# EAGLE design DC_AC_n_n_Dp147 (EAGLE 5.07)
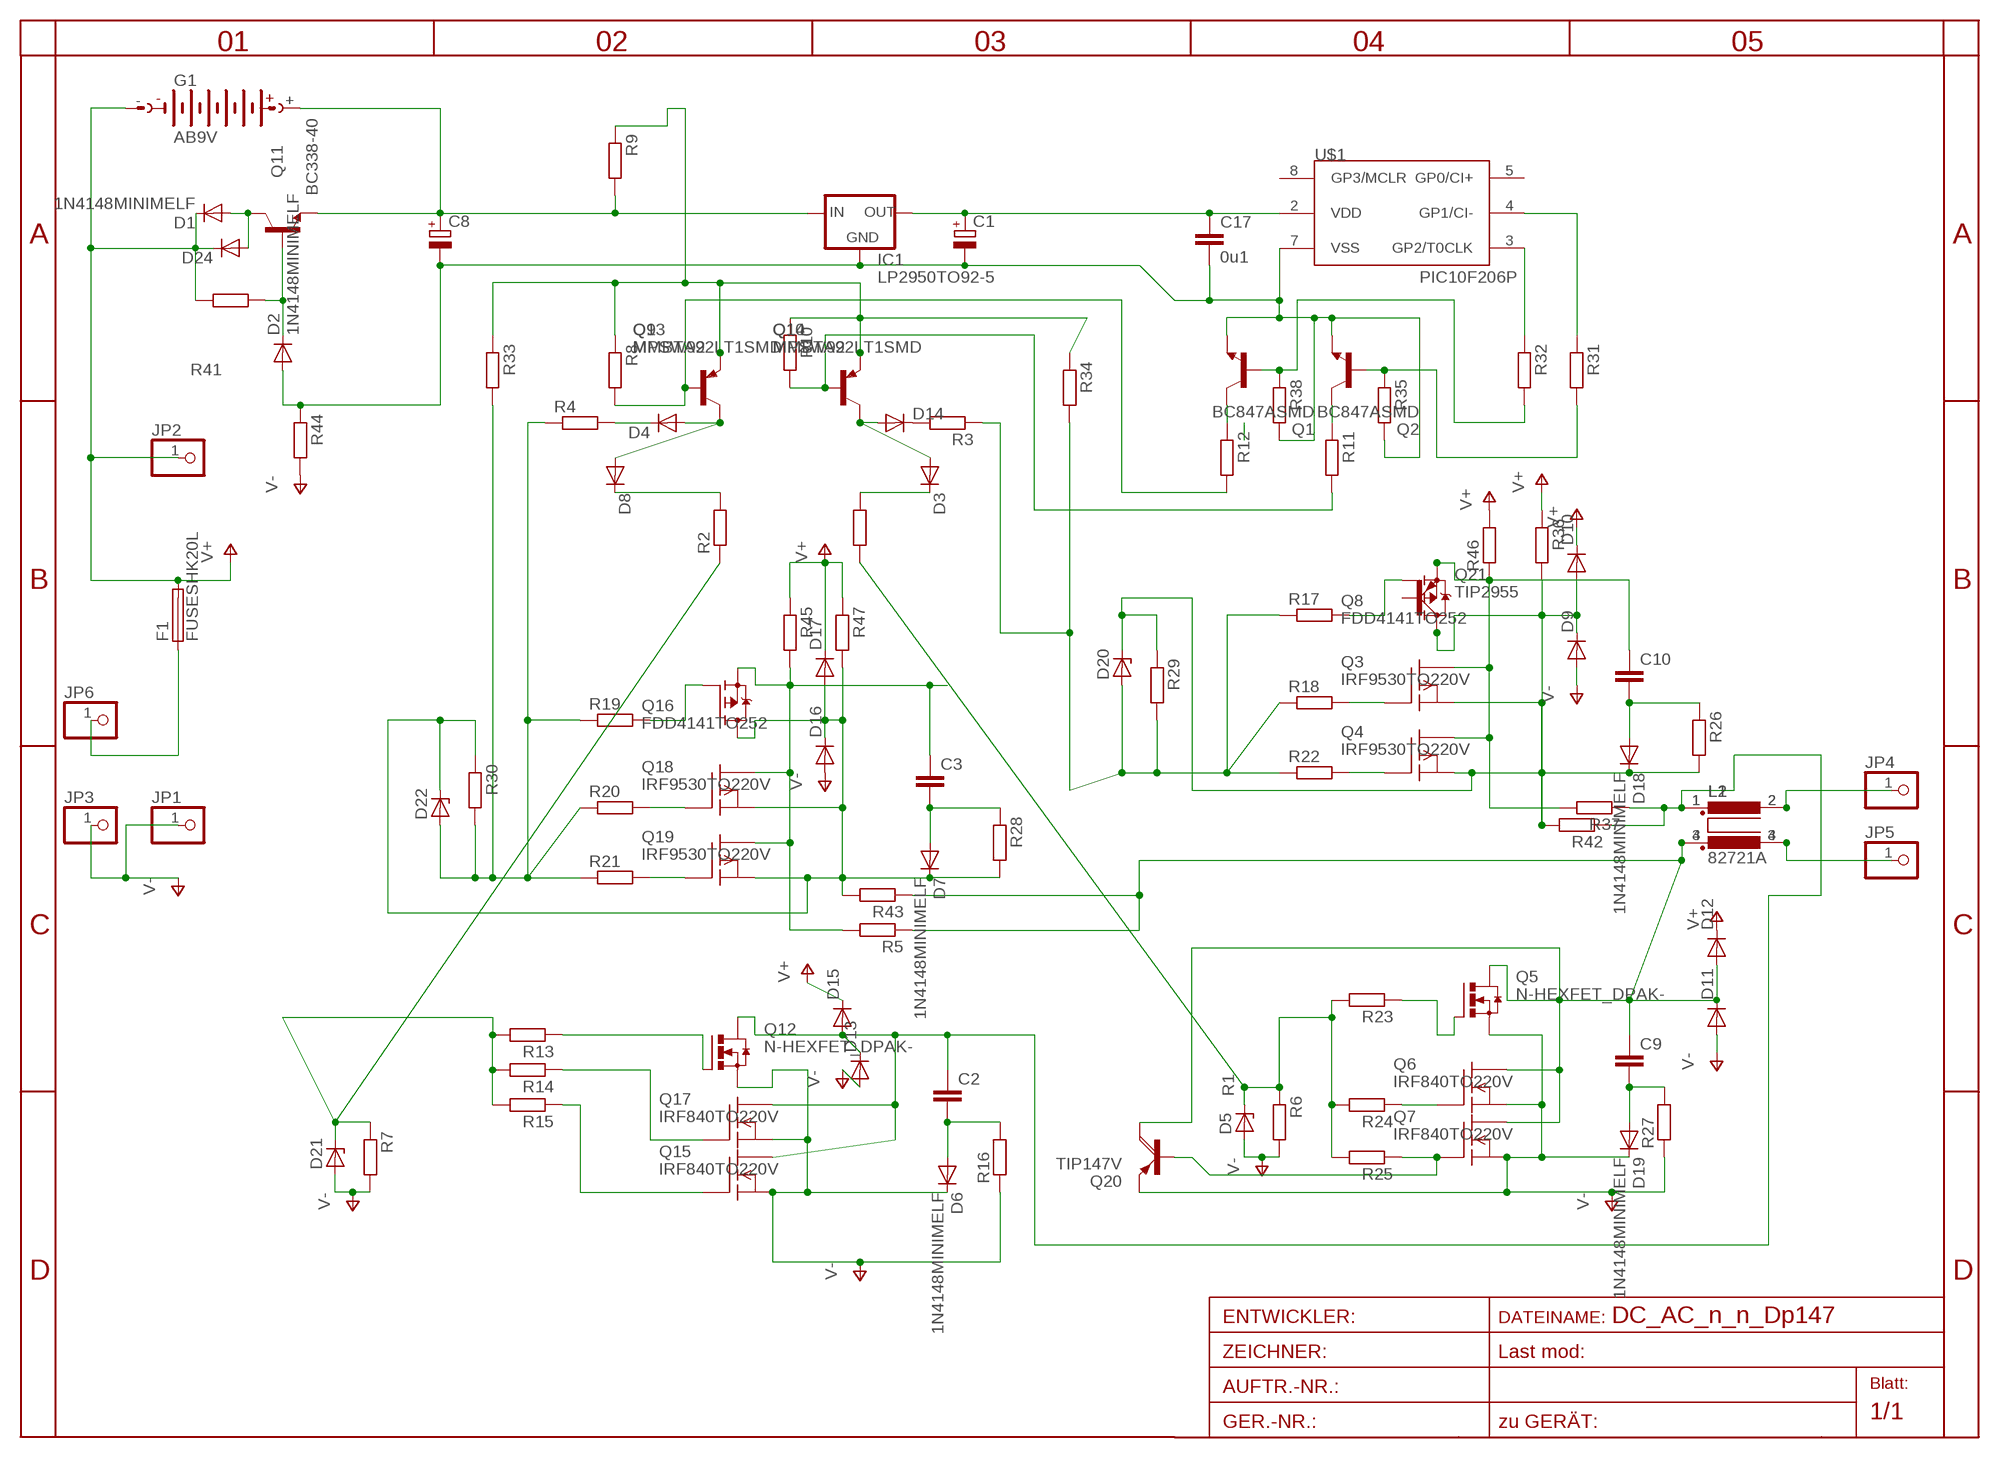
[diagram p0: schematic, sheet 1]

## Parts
C1  CPOL-EU5-13  [2,5-5-FLAT]
C2  C-EUC1812  [C1812]
C3  C-EUC1812K  [C1812K]
C8  CPOL-EUE2.5-7  [E2,5-7]
C9  C-EUC1812  [C1812]
C10  C-EUC1812K  [C1812K]
C17  0u1  C-EUC1206  [C1206]
D1  1N4148MINIMELF  [MINIMELF]
D2  1N4148MINIMELF  [MINIMELF]
D3  DIODE-SMB  [SMB]
D4  DIODE-SMB  [SMB]
D5  ZENER-DIODESOD80C  [SOD80C]
D6  1N4148MINIMELF  [MINIMELF]
D7  1N4148MINIMELF  [MINIMELF]
D8  DIODE-SMB  [SMB]
D9  DIODE-SMC  [SMC]
D10  DIODE-SMC  [SMC]
D11  DIODE-SMC  [SMC]
D12  DIODE-SMC  [SMC]
D13  DIODE-SMC  [SMC]
D14  DIODE-SMB  [SMB]
D15  DIODE-SMC  [SMC]
D16  DIODE-SMC  [SMC]
D17  DIODE-SMC  [SMC]
D18  1N4148MINIMELF  [MINIMELF]
D19  1N4148MINIMELF  [MINIMELF]
D20  ZENER-DIODESOD80C  [SOD80C]
D21  ZENER-DIODESOD80C  [SOD80C]
D22  ZENER-DIODESOD80C  [SOD80C]
D24  DIODE-D-7.5  [D-7.5]
F1  FUSESHK20L  [SHK20L]
G1  AB9V  [AB9V]
IC1  LP2950TO92-5  [T092-5]
JP1  PINHD-1X11MM6  [1X1MM8]
JP2  PINHD-1X11MM6  [1X1MM8]
JP3  PINHD-1X11MM6  [1X1MM8]
JP4  PINHD-1X14.5MM  [1X4MM5]
JP5  PINHD-1X14.5MM  [1X4MM5]
JP6  PINHD-1X11MM6  [1X1MM8]
L1  R1405VB2  [B2]
L2  82721A  [82721A]
Q1  BC847ASMD  [SOT23]
Q2  BC847ASMD  [SOT23]
Q3  IRF9530TO220V  [TO220V]
Q4  IRF9530TO220V  [TO220V]
Q5  N-HEXFET_DPAK-  [TO252]
Q6  IRF840TO220V  [TO220V]
Q7  IRF840TO220V  [TO220V]
Q8  FDD4141TO252  [TO252]
Q9  MPSW92  [TO92-CBE]
Q10  MPSW92  [TO92-CBE]
Q11  BC338-40  [TO92-EBC]
Q12  N-HEXFET_DPAK-  [TO252]
Q13  MMBTA92LT1SMD  [SOT23-BEC]
Q14  MMBTA92LT1SMD  [SOT23-BEC]
Q15  IRF840TO220V  [TO220V]
Q16  FDD4141TO252  [TO252]
Q17  IRF840TO220V  [TO220V]
Q18  IRF9530TO220V  [TO220V]
Q19  IRF9530TO220V  [TO220V]
Q20  TIP147V  [SOT93V]
Q21  TIP2955  [TOP3AV]
R1  R-EU_R1206  [R1206]
R2  R-EU_R1206  [R1206]
R3  R-EU_R1206  [R1206]
R4  R-EU_R1206  [R1206]
R5  R-EU_0207/30  [0207/30]
R6  R-EU_R1206  [R1206]
R7  R-EU_R1206  [R1206]
R8  R-EU_R1206  [R1206]
R9  R-EU_0207/10  [0207/10]
R10  R-EU_R1206  [R1206]
R11  R-EU_R1206  [R1206]
R12  R-EU_R1206  [R1206]
R13  R-EU_R1206  [R1206]
R14  R-EU_R1206  [R1206]
R15  R-EU_R1206  [R1206]
R16  R-EU_R1206  [R1206]
R17  R-EU_R1206  [R1206]
R18  R-EU_R1206  [R1206]
R19  R-EU_R1206  [R1206]
R20  R-EU_R1206  [R1206]
R21  R-EU_R1206  [R1206]
R22  R-EU_R1206  [R1206]
R23  R-EU_R1206  [R1206]
R24  R-EU_R1206  [R1206]
R25  R-EU_R1206  [R1206]
R26  R-EU_R1206  [R1206]
R27  R-EU_R1206  [R1206]
R28  R-EU_R1206  [R1206]
R29  R-EU_R1206  [R1206]
R30  R-EU_R1206  [R1206]
R31  R-EU_R1206  [R1206]
R32  R-EU_R1206  [R1206]
R33  R-EU_0207/30  [0207/30]
R34  R-EU_R1206  [R1206]
R35  R-EU_R0805  [R0805]
R36  R-EU_0207/10  [0207/10]
R37  R-EU_0207/10  [0207/10]
R38  R-EU_R0805  [R0805]
R41  R-EU_R1206  [R1206]
R42  R-EU_0207/15  [0207/15]
R43  R-EU_0207/30  [0207/30]
R44  R-EU_R1206  [R1206]
R45  R-EU_0204/5  [0204/5]
R46  R-EU_0204/5  [0204/5]
R47  R-EU_0204/5  [0204/5]
U$1  PIC10F206P  [DIL8]

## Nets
AC1: JP4.1 L1.2 L2.2
AC2: JP5.1 L1.4 L2.3
BATT+: C8.+ G1.+ IC1.3(IN) Q11.E R9.2
FNGATE2: D4.C R4.2
N$1: F1.1A JP6.1
N$2: C3.1 Q16.3(S) Q18.2(D) Q19.2(D) R5.2 R45.2
N$3: Q1.3(C) R12.1
N$4: Q3.1(G) R18.2
N$5: C1.+ C17.1 IC1.1(OUT) U$1.2(VDD)
N$6: D8.C R2.2
N$7: Q2.3(C) R11.1
N$8: D3.C R1.2
N$10: D5.C R1.1 R6.1 R23.2 R24.2 R25.2
N$11: Q8.1(G) R17.2
N$13: Q15.1(G) R15.1
N$15: Q17.1(G) R14.1
N$16: Q9.B Q13.B R8.2 R12.2
N$18: D4.A D8.A Q9.C Q13.C
N$19: Q10.B Q14.B R10.2 R11.2
N$21: D3.A D14.A Q10.C Q14.C
N$22: Q12.1(G) R13.1
N$23: Q4.1(G) R22.2
N$24: C10.2 D18.A R26.1
N$25: Q7.1(G) Q20.B R25.1
N$26: Q6.1(G) R24.1
N$27: Q5.1(G) R23.1
N$28: C9.2 D19.A R27.2
N$29: C2.2 D6.A R16.2
N$30: D7.C D16.C D17.A D22.C Q16.2(D) Q18.3(S) Q19.3(S) R28.2 R30.1 R43.2 R47.2
N$32: Q18.1(G) R20.2
N$33: Q19.1(G) R21.2
N$34: Q16.1(G) R19.2
N$35: C3.2 D7.A R28.1
N$36: D1.A D24.A Q11.C
N$38: D2.C Q11.B R41.1
N$39: R31.1 U$1.4(GP1/CI-)
N$42: Q2.1(B) R31.2 R35.1
N$43: R32.1 U$1.3(GP2/T0CLK)
N$45: Q1.1(B) R32.2 R38.1
N-GATE: D14.C R3.2
NDRAIN2: C2.1 D13.C D15.A L1.1 L2.1 Q12.3(D) Q15.2(D) Q17.2(D) R37.1 R42.1
NGATE2: D21.C R2.1 R7.1 R13.2 R14.2 R15.2
O1: C9.1 D11.C D12.A L1.3 L2.4 Q5.3(D) Q6.2(D) Q7.2(D) Q20.C R5.1 R43.1
P1E: D9.C D10.A D18.C D20.C Q3.3(S) Q4.3(S) Q8.2(D) Q21.C R26.2 R29.1 R36.2 R42.2
P-: C1.- C8.- C17.2 D2.A IC1.2(GND) Q1.2(E) Q2.2(E) R35.2 R38.2 R44.1 U$1.7(VSS)
PDRAIN1: C10.1 Q3.2(D) Q4.2(D) Q8.3(S) Q21.E R37.2 R46.1
PGATE1: D20.A R3.1 R17.1 R18.1 R22.1 R29.2 R34.2
PGATE2: D22.A R4.1 R19.1 R20.1 R21.1 R30.2 R33.2
V+: D1.C D10.C D12.C D15.C D17.C D24.C F1.2A G1.- JP2.1 R36.1 R41.2 R45.1 R46.2 R47.1
V-: D5.A D6.C D9.A D11.A D13.A D16.A D19.C D21.A JP1.1 JP3.1 Q5.2(S) Q6.3(S) Q7.3(S) Q12.2(S) Q15.3(S) Q17.3(S) Q20.E R6.2 R7.2 R16.1 R27.1 R44.2
VHIGH: Q9.E Q10.E Q13.E Q14.E R8.1 R9.1 R10.1 R33.1 R34.1
Unconnected: Q21.B U$1.5(GP0/CI+) U$1.8(GP3/MCLR)

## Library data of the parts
C1 C8 = rcl-2:CPOL-EU: POLARIZED CAPACITOR, European symbol
C2 C3 C9 C10 C17 = rcl-2:C-EU: CAPACITOR, European symbol
D1 D2 D6 D7 D18 D19 = diode-1:1N4148: DIODE
D3 D4 D8-D17 = diode:DIODE-: DIODE
D5 D20-D22 = diode:ZENER-DIODE: Z-Diode
D24 = diode-1:DIODE-: DIODE
F1 = fuse:FUSE: Fuse
G1 = battery:AB9V: 9-V BATTERY CLIP
IC1 = v-reg:LP2950?*: Source: http://cache.national.com/ds/LP/LP2950.pdf
JP1-JP6 = pinhead:PINHD-1X1: PIN HEADER
L1 = inductor-nkl:R1405V: Übertrager (verlustarm) bis typ. 400kHz Power transformer (low loss) up to typ. 400kHz
L2 = inductors:82721A: FILTER
Q1 Q2 = transistor-npn:BC847*: NPN Transistor
Q3 Q4 Q18 Q19 = transistor-fet:IRF9530: P-Channel Enhancement MOSFET (HEXFET); -100V; -12A; 0,3Ohm
Q5 Q12 = transistor-power:N-HEXFET_?-*: HEXFET® Power MOSFET
Q6 Q7 Q15 Q17 = transistor-fet:IRF840: N-Channel Enhancement MOSFET (HEXFET); 500V; 8A; 0,85Ohm
Q8 Q16 = transistor-fet:FDD4141: P-Channel PowerTrench® MOSFET Source: FDD4141.pdf
Q9 Q10 = transistor-pnp:MPSW92*: PNP Transistror
Q11 = transistor-npn:BC338*: NPN Transistor
Q13 Q14 = transistor-pnp:MMBTA92*: PNP Transistror
Q20 = transistor-power:TIP147: PNP DARLINGTON TRANSISTOR
Q21 = transistor-power:TIP2955: PNP TRANSISTOR
R1-R38 R41-R47 = rcl-2:R-EU_: RESISTOR, European symbol
U$1 = microchip-5:PIC10F2*: uPC nW 0,25/0,5k Program Flash memory Comparator

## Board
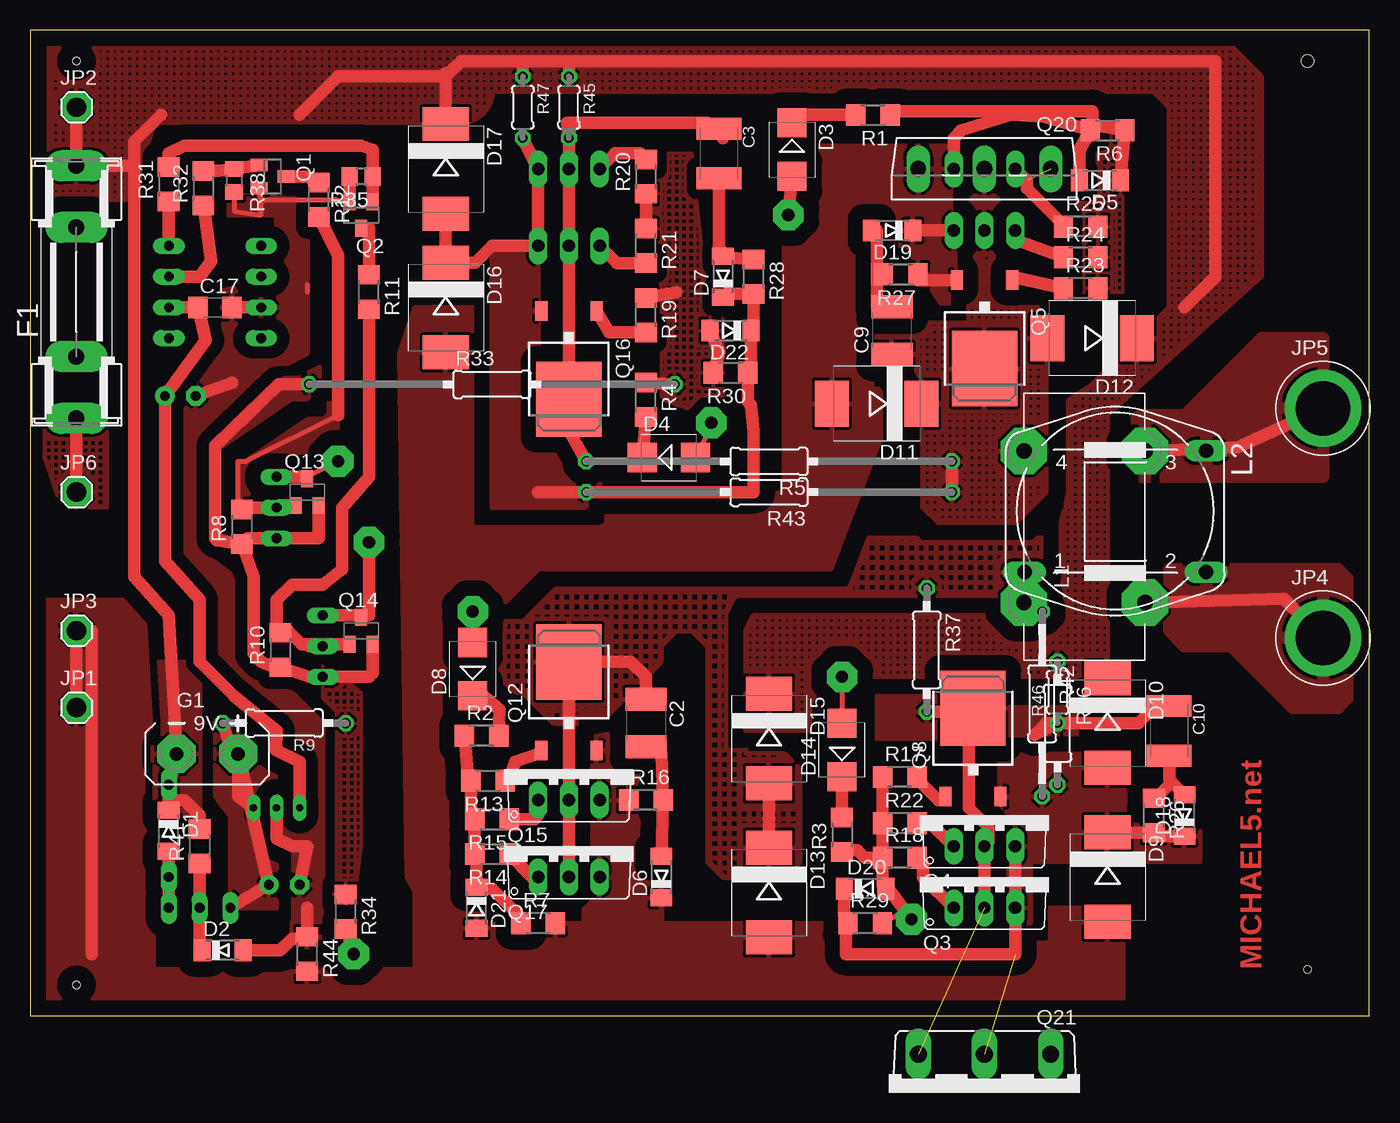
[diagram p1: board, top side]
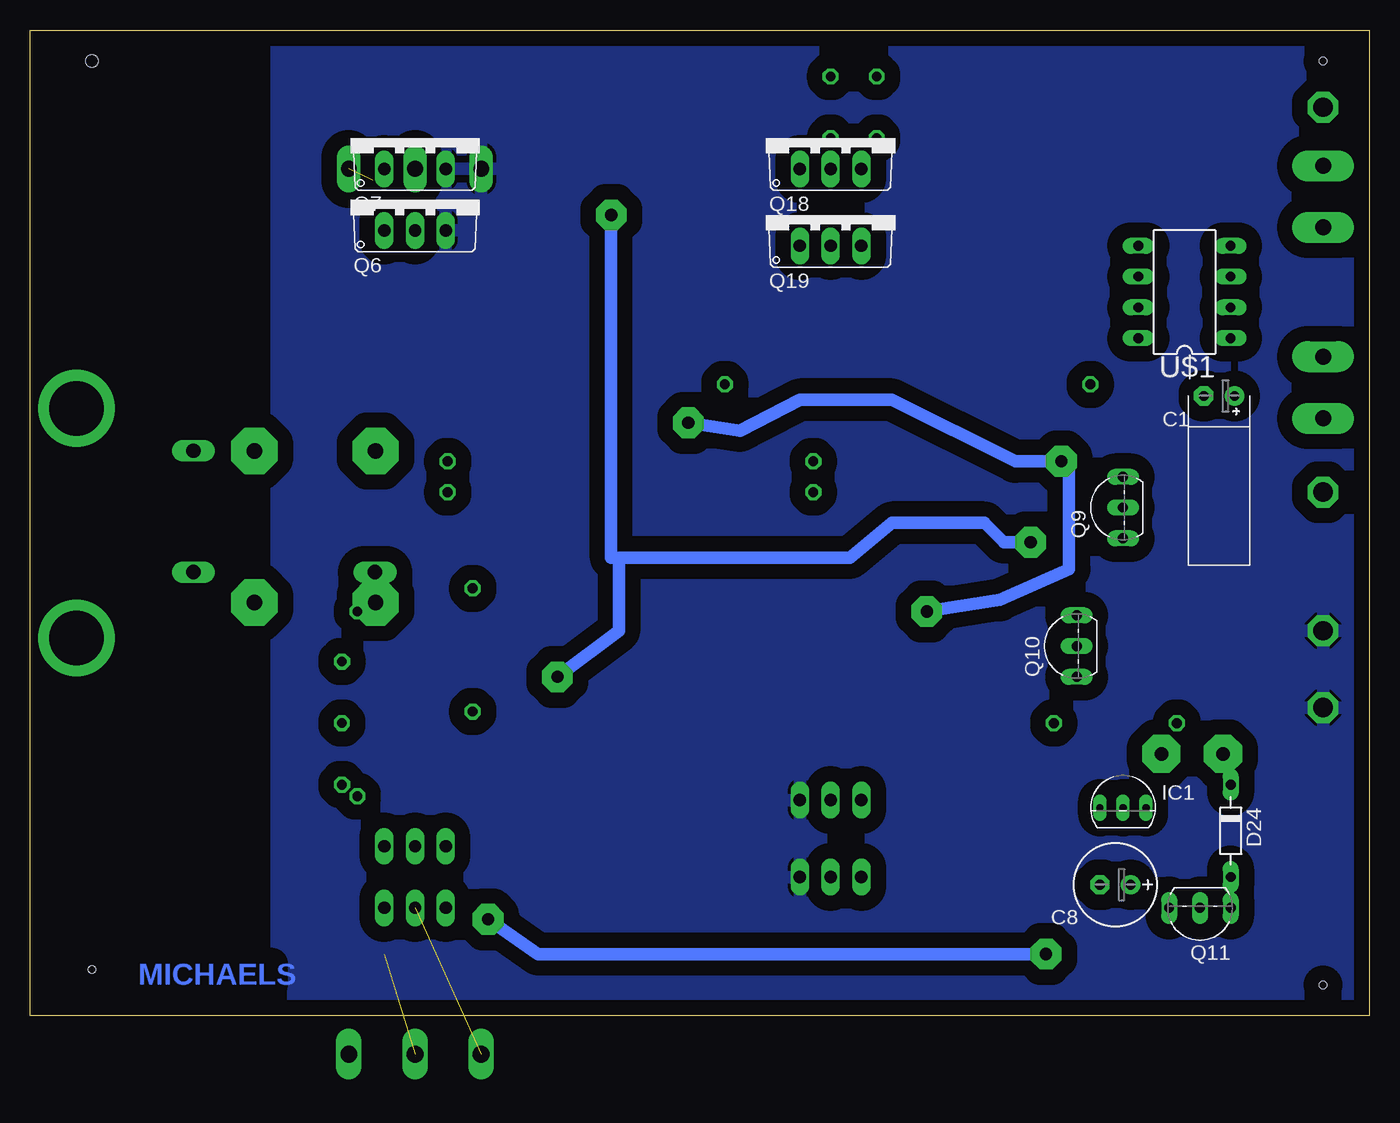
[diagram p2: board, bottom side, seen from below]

Size 110.49 x 81.28 mm. Coordinates in mm from the lower left corner, seen from the top.
Outline: 0,0 110.49,0 110.49,81.28 0,81.28 0,0
Copper layers (1*16): Top 0.035mm / dielectric 1.5mm / Bottom 0.035mm
Design rules "default *": minimum track width 12mil, minimum drill 24mil, track to track 8mil, track to pad 8mil, pad to pad 8mil, via to via 8mil, smd to smd 8mil, copper to edge 40mil, drill to drill 8mil, minimum pad ring 10mil, minimum via ring 8mil, stop-mask expansion 4mil, vias tented up to drill 0mil, thermal gap 10mil
Holes 0.6 mm at 3.81,78.74 3.81,2.54 105.41,3.81
Holes 1 mm at 105.41,78.74

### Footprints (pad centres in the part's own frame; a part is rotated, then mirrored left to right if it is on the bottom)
2,5-5-FLAT = drill 0.813 pad 1.6 round: + -1.27,0 | drill 0.813 pad 1.6 octagon: - 1.27,0
C1812 = smd 1.9 x 3.4: 1 -1.95,0; 2 1.95,0
C1812K = smd 1.8 x 3.7: 1 -2.05,0; 2 2.05,0
E2,5-7 = drill 0.813 pad 1.6 round: + -1.27,0 | drill 0.813 pad 1.6 octagon: - 1.27,0
C1206 = smd 1.6 x 1.8: 1 -1.4,0; 2 1.4,0
MINIMELF = smd 1.4 x 1.8: A 1.7,0; C -1.7,0
SMB = smd 2.4 x 2.4: A 2.2,0; C -2.2,0
SOD80C = smd 1.4 x 1.8: A 1.7,0; C -1.7,0
SMC = smd 2.8 x 3.8: A 3.7,0; C -3.7,0
D-7.5 = drill 0.813 long: A 3.81,0; C -3.81,0
SHK20L = drill 1.321 pad 2.54 long: 1A -10.414,0; 1B -5.334,0; 2A 10.414,0; 2B 5.334,0
AB9V = drill 1.118 pad 3.15 octagon: + 0,2.54; - 0,-2.54
T092-5 = drill 0.6 pad 0.813 long: 1 -1.905,0; 2 0,0; 3 1.905,0
1X1MM8 = drill 1.6 pad 2.54 octagon: 1 0,0
1X4MM5 = drill 4.5 pad 6.35 round: 1 0,0
B2 = drill 1.27 pad 3.81 octagon: 1 -6.25,5; 2 -6.25,-5; 3 6.25,5; 4 6.25,-5
82721A = drill 1.194 long: 1 7.493,5.004; 2 -7.493,5.004; 3 -7.493,-5.004; 4 7.493,-5.004
SOT23 = smd 1 x 1.4: 1 -0.95,-1.1; 2 0.95,-1.1; 3 0,1.1
TO220V = drill 1.016 long: 1 -2.54,-2.54; 2 0,-2.54; 3 2.54,-2.54
TO252 = smd 1 x 1.6: 1 -2.28,-3.53; 2 2.28,-3.53 | smd 5.4 x 6.2: 3 0,3.77
TO252' = smd 1 x 1.6: 1 -2.28,-4.8; 2 2.28,-4.8 | smd 5.4 x 6.2: 3 0,2.5
TO92-CBE = drill 0.813 long: B 0,0; C 2.54,0; E -2.54,0
TO92-EBC = drill 0.813 long: B 0,-1.27; C -2.54,-1.27; E 2.54,-1.27
SOT23-BEC = smd 1 x 1.4: B -0.95,-1.1; C 0,1.1; E 0.95,-1.1
SOT93V = drill 1.3 pad 1.676 long: B -5.461,-2.54; C 0,-2.54; E 5.461,-2.54
TOP3AV = drill 1.397 long: B -5.461,-3.175; C 0,-3.175; E 5.461,-3.175
R1206 = smd 1.6 x 1.803: 1 -1.422,0; 2 1.422,0
0207/30 = drill 0.813 octagon: 1 -15.08,0; 2 15.08,0
0207/10 = drill 0.813 octagon: 1 -5.08,0; 2 5.08,0
R0805 = smd 1.3 x 1.5: 1 -0.95,0; 2 0.95,0
0207/15 = drill 0.8 pad 1.27 octagon: 1 -7.62,0; 2 7.62,0
0204/5 = drill 0.8 pad 1.27 octagon: 1 -2.54,0; 2 2.54,0
DIL8 = drill 0.8 long: 1 -3.81,-3.81; 2 -1.27,-3.81; 3 1.27,-3.81; 4 3.81,-3.81; 5 3.81,3.81; 6 1.27,3.81; 7 -1.27,3.81; 8 -3.81,3.81

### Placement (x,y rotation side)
C1  12.38,51.12 180 bottom
C2  50.8,24.13 270 top
C3  56.83,71.12 270 top
C8  20.95,10.79 180 bottom
C9  71.12,56.52 90 top
C10  93.98,23.5 270 top
C17  15.24,58.42 0 top
D1  11.43,15.24 270 top
D2  15.88,5.4 0 top
D3  62.87,71.44 270 top
D4  52.7,46.04 0 top
D5  88.27,68.9 180 top
D6  52.07,11.43 90 top
D7  57.15,60.96 90 top
D8  36.51,28.57 90 top
D9  88.9,11.43 270 top
D10  88.9,24.13 270 top
D11  69.85,50.48 180 top
D12  87.63,55.88 180 top
D13  60.96,10.16 270 top
D14  66.99,21.91 90 top
D15  60.96,22.86 270 top
D16  34.29,58.42 270 top
D17  34.29,69.85 270 top
D18  95.25,16.51 90 top
D19  71.12,64.77 180 top
D20  68.9,10.48 0 top
D21  36.83,8.89 270 top
D22  57.78,56.52 180 top
D24  11.43,15.24 270 bottom
F1  3.81,59.69 90 top
G1  14.61,21.59 270 top
IC1  20.32,17.14 0 bottom
JP1  3.81,25.4 0 top
JP2  3.81,74.93 0 top
JP3  3.81,31.75 0 top
JP4  106.68,31.15 0 top
JP5  106.68,50.1 0 top
JP6  3.81,43.18 0 top
L1  87,40.32 90 top
L2  89.53,41.59 180 top
Q1  20,69.22 270 top
Q2  27.3,66.04 180 top
Q3  78.74,11.43 0 top
Q4  78.74,16.51 0 top
Q5  78.74,57.15 180 top
Q6  78.74,67.31 0 bottom
Q7  78.74,72.39 0 bottom
Q8  FDD4141TO252  [TO252']  77.79,22.86 0 top
Q9  20.32,41.91 90 bottom
Q10  24.13,30.48 90 bottom
Q11  13.97,7.62 180 bottom
Q12  44.45,25.4 0 top
Q13  22.86,43.18 0 top
Q14  27.3,31.75 0 top
Q15  44.45,20.32 0 top
Q16  FDD4141TO252  [TO252']  44.45,53.34 180 top
Q17  44.45,13.97 0 top
Q18  44.45,72.39 0 bottom
Q19  44.45,66.04 0 bottom
Q20  78.74,67.31 180 top
Q21  not placed on the board
R1  69.53,74.3 180 top
R2  37.24,23.08 0 top
R3  66.99,14.92 90 top
R4  50.8,50.8 270 top
R5  60.96,45.72 180 top
R6  88.9,73.03 180 top
R7  41.91,7.62 0 top
R8  17.46,40.32 90 top
R9  20.95,24.13 180 top
R10  20.64,30.16 90 top
R11  27.94,59.69 270 top
R12  23.81,67.31 270 top
R13  37.78,19.37 180 top
R14  38.1,13.34 180 top
R15  38.1,16.19 180 top
R16  50.8,17.78 0 top
R17  71.75,19.68 0 top
R18  71.75,13.02 0 top
R19  50.8,57.78 270 top
R20  50.8,69.22 90 top
R21  50.8,63.5 270 top
R22  71.75,15.88 0 top
R23  86.68,60.01 0 top
R24  86.68,62.55 0 top
R25  86.68,65.09 0 top
R26  92.71,16.51 270 top
R27  71.82,61.15 180 top
R28  59.69,60.96 270 top
R29  68.9,7.62 0 top
R30  57.78,53.02 180 top
R31  11.43,68.58 90 top
R32  14.29,68.26 90 top
R33  38.1,52.07 0 top
R34  26.04,8.57 270 top
R35  27.3,69.22 180 top
R36  84.77,24.13 270 top
R37  73.98,30.16 270 top
R38  16.83,68.9 270 top
R41  13.97,13.97 90 top
R42  83.5,25.72 270 top
R43  60.96,43.18 180 top
R44  22.86,5.08 270 top
R45  44.45,74.93 270 top
R46  84.77,26.67 90 top
R47  40.64,74.93 270 top
U$1  15.24,59.69 90 bottom

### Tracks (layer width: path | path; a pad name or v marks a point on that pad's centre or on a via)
AC1
  Top 1.016: L1.2 103.44,34.39 JP4.1
  pour Top (isolate 1.27, rank 3, hatched): 93.98,36.83 107.95,36.83 109.22,35.56 109.22,26.67 107.95,25.4 104.14,25.4 99.06,30.48 95.25,30.48 93.98,31.75
AC2
  Top 1.016: L1.4 99.66,46.89 JP5.1
  pour Top (isolate 0.813, rank 3, hatched): 88.9,48.26 90.17,49.53 95.25,49.53 101.6,55.88 106.68,55.88 106.68,44.45 88.9,44.45
BATT+
  Top 1.016: Q11.E C8.+ G1.+ | G1.+ 16.51,22.23 R9.2 | IC1.3 17.14,18.1 G1.+
  pour Top (isolate 1.27): 15.24,24.13 15.24,17.78 16.51,16.51 16.51,8.89 20.32,8.89 20.32,21.59
FNGATE2
  Top 1.016: D4.C R4.2
N$1
  Top 1.016: JP6.1 F1.1A
  pour Top (isolate 0.813, rank 3, hatched): 0,48.26 6.35,48.26 6.35,41.91 2.54,41.91 1.27,45.72
N$2
  Top 1.016: R45.2 Q18.2 Q19.2 Q16.3 44.45,48.26 R5.2 | R45.2 44.3,73.66 | C3.1 57.15,72.39 55.88,73.66 44.6,73.66 R45.2
N$3
  Top 1.016: Q1.3 22.84,69.22 R12.1
N$4
  Top 1.016: Q3.1 73.66,11.43 73.66,12.53 R18.2
N$5
  Top 1.016: U$1.2 C17.1 14.47,55.69 C1.+ 11.11,37.47 13.97,34.29 13.97,29.21 16.83,26.35 20.32,23.5 20.31,21.9 22.23,20.94 IC1.1
N$6
  Top 1.016: D8.C 36.83,26.35 37.47,26.35 38.73,25.25 R2.2
N$7
  Top 0.406: 27.94,64.94 Q2.3
  Top 1.016: R11.1 27.94,64.94
N$8
  Top 1.016: R1.2 63.84,74.3 D3.C
N$10
  Top 1.016: D5.C R6.1 87.63,73.51 87.63,74.61 70.8,74.61 R1.1
  pour Top (isolate 0.813, rank 3, hatched): 86.36,73.66 90.17,73.66 90.17,59.69 86.36,59.69
N$11
  Top 1.016: R17.2 73.18,19.53 74.93,17.78 75.23,17.78 Q8.1
N$13
  Top 0.406: 41.59,16.19 41.91,16.51
  Top 1.016: R15.1 41.59,16.19 | 41.91,16.51 Q15.1
N$15
  Top 1.016: Q17.1 41.43,11.43 R14.1
N$16
  Top 0.406: 25.4,49.53 17.78,45.72 17.14,45.72 17.14,42.06 R8.2
  Top 1.016: R8.2 17.93,41.91 Q9.B 20.49,42.08 Q13.B | R12.2 25.4,62.71 25.4,49.53
  pour Top (isolate 1.27, rank 4): 21.59,50.8 25.4,53.34 25.4,48.26 16.51,41.91 16.51,45.72
N$18  (via drill 1 pad 2.54)
  Top 0.406: Q13.C 22.86,44.45 v25.4,45.72 | v36.51,33.34 D8.A | D4.A 56.22,48.6 v56.2,48.9
  Top 1.016: Q13.C 22.69,44.45 Q9.C
  Bottom 1.016: v36.51,33.34 30.48,34.29 24.77,36.83 24.77,45.72 v25.4,45.72 29.21,45.72 39.37,50.8 46.99,50.8 51.94,48.26 v56.2,48.9
N$19
  Top 0.406: R10.2 20.32,31.9
  Top 1.016: 23.01,30.48 Q10.B 23.03,30.65 | 23.03,30.65 Q14.B | 23.03,30.65 22.37,30.65 21.27,31.75 20.8,31.75 R10.2 | R11.2 27.94,44.45 25.72,41.91 25.72,36.83 24.13,35.56 21.59,35.56 20.32,34.29 20.32,31.9
N$21  (via drill 1 pad 2.54)
  Top 0.406: v66.99,27.94 D14.A | Q14.C 27.77,32.85 27.94,33.02
  Top 1.016: Q10.C 27.94,33.02 v27.94,39.05 | v62.55,66.04 D3.A
  Bottom 1.016: v27.94,39.05 30.16,39.05 31.75,40.64 39.37,40.64 42.86,37.78 61.91,37.78 | 61.91,37.78 62.55,37.78 v62.55,66.04 | v66.99,27.94 61.91,31.75 61.91,37.78
N$22
  Top 0.406: R13.1 39.52,19.52 | 41.89,21.59 Q12.1
  Top 1.016: 39.52,19.52 40.01,20.95 41.89,21.59
N$23
  Top 1.016: Q4.1 74.3,15.88 R22.2
N$24
  Top 1.016: C10.2 93.98,19.48 94.19,19.27 | 94.19,19.27 D18.A | R26.1 92.86,17.93 94.19,19.27
N$25  (1 unrouted)
  Top 1.016: R25.1 85.25,65.24 82.23,68.26 82.23,68.9 Q7.1
N$26
  Top 1.016: R24.1 81.28,63.98 Q6.1
N$27
  Top 1.016: R23.1 81.02,60.96 Q5.1
N$28
  Top 1.016: D19.A 69.85,64.77 69.85,60.96 70.4,60.96 R27.2 69.85,61.15 69.85,58.42 71.12,58.42 C9.2
N$29
  Top 1.016: D6.A R16.2 52.07,21.59 C2.2
N$30
  Top 1.016: 41.91,43.18 R43.2 59.69,43.18 59.69,48.26 59.48,50.37 59.21,50.65 R30.1 59.48,53.3 D22.C 59.69,56.72 R28.2 57.43,59.54 D7.C | R47.2 Q18.3 Q19.3 38.1,63.5 36.72,62.12 D16.C D17.A
  pour Top (isolate 1.27): 41.91,63.5 41.91,46.99 44.45,45.72 45.72,45.72 46.99,44.45 46.99,43.18 45.72,41.91 38.1,41.91 38.1,63.5
N$32
  Top 1.016: Q18.1 48.26,71.12 50.32,71.12 R20.2
N$33
  Top 1.016: R21.2 48.41,62.08 Q19.1
N$34
  Top 1.016: R19.2 47.78,56.36 Q16.1
N$35
  Top 1.016: C3.2 56.83,63.5 D7.A 57.15,62.55 R28.1
N$36
  Top 1.016: D1.A D24.A Q11.C
N$38
  Top 1.016: R41.1 Q11.B 13.97,5.6 D2.C
N$39
  Top 1.016: U$1.4 R31.1
N$42
  Top 0.406: 28.26,69.53 R35.1
  Top 1.016: R31.2 11.43,71.12 12.7,71.75 27.3,71.75 28.26,71.44 28.26,69.53 | R35.1 Q2.1
N$43
  Top 1.016: U$1.3 13.97,60.96 14.92,62.23 R32.1
N$45
  Top 1.016: R32.2 15.56,69.68 R38.1 Q1.1
N-GATE
  Top 1.016: R3.2 D14.C
NDRAIN2
  Top 1.016: D13.C D15.A | C2.1 50.8,27.94 49.53,29.21 44.49,29.21 Q12.3 Q15.2 Q17.2 | L2.1 82,36.32 L1.1 82.77,34.07 R42.1
  pour Top (isolate 1.27, rank 3, hatched): 35.56,26.67 40.64,26.67 43.18,24.13 46.99,24.13 52.07,29.21 52.07,30.48 53.34,31.75 54.61,31.75 55.88,30.48 55.88,12.7 57.15,11.43 62.23,11.43 63.5,12.7 63.5,20.32 62.23,21.59 59.05,21.59 59.05,30.48 59.69,31.75 83.82,31.75 83.82,39.37 66.04,39.37 63.5,36.83 41.91,36.83 38.1,33.02
NGATE2
  Top 0.406: 36.83,13.18 R14.2 | 40.49,8.09 R7.1 | D21.C 36.94,10.48
  Top 1.016: R14.2 R15.2 36.36,16.51 R13.2 36.14,19.59 R2.1 | D21.C 36.83,13.18 | 40.49,8.09 38.1,10.48 36.94,10.48
O1
  Top 1.016: R43.1 R5.1
  pour Top (isolate 1.27, hatched): 69.85,57.15 77.47,57.15 77.47,73.66 80.01,73.66 80.01,58.42 83.82,58.42 83.82,43.18 81.28,40.64 74.93,40.64 73.66,41.91 73.66,52.07 73.03,53.34 69.85,53.34
P1E  (1 unrouted)
  Top 1.016: Q4.3 Q3.3 81.28,5.08 67.31,5.08 67.31,7.47 R29.1 67.16,8.29 D20.C | D18.C 92.99,14.81 R26.2 89.05,15.09 88.9,15.24 D9.C
  pour Top (isolate 1.27): 80.01,21.59 91.44,21.59 91.44,15.24 96.52,15.24 96.52,12.7 82.55,12.7 82.55,7.62 80.01,7.62
P-
  Top 0.406: 22.86,60.33 22.86,59.69 | Q2.2 25.23,67.31 19.05,67.31 | R38.2 16.83,66.36 19.05,66.04 19.05,67.31 | 19.05,67.31 Q1.2
  Top 1.016: C1.- 16.64,52.2 | C17.2 U$1.7 | D2.A 20.64,5.4 21.59,6.35 22.71,6.35 R44.1 22.86,8.89 | IC1.2 20.32,14.61 21.59,13.97 22.86,13.97 C8.- | Q2.2 R35.2
  pour Top (isolate 1.016, rank 2): 20.32,66.04 15.88,66.04 15.24,66.67 15.24,67.63 22.86,67.63 22.86,54.61 20.32,53.34 14.29,48.26 14.29,38.1 17.78,35.56 17.78,30.48 24.13,24.13 24.13,5.08 22.86,5.08 21.59,6.35 21.59,12.7 19.05,13.97 19.05,15.24 20.32,16.51 20.32,24.13 16.51,24.13 16.51,25.4 15.24,26.67 15.24,33.02 11.43,36.83 11.43,52.07 12.7,53.34 13.97,53.34 15.24,54.61 15.24,59.69 20.32,60.96
PDRAIN1  (1 unrouted)
  Top 1.016: Q3.2 Q4.2 79.06,14.29 79.06,15.56 77.47,17.14 77.47,25.36 Q8.3 77.51,25.08 R37.2 | R46.1 82.87,23.18 83.82,24.13 91.44,24.13 92.71,25.4 93.83,25.4 C10.1
  pour Top (isolate 1.27, rank 3): 69.85,27.94 69.85,22.86 86.36,22.86 86.36,25.4 76.2,25.4 76.2,27.94
PGATE1  (via drill 1 pad 2.54)
  Top 0.406: R34.2 26.04,5.71 v26.67,5.08 | v72.71,7.94 72.39,8.74 R29.2
  Top 1.016: R17.1 R22.1 R18.1 | R18.1 68.9,13.02 68.26,13.65 67.14,13.65 R3.1 | R18.1 70.33,10.74 D20.A 70.8,10.48 v72.71,7.94
  Bottom 1.016: v26.67,5.08 68.58,5.08 v72.71,7.94
PGATE2
  Top 1.016: R21.1 R20.1 | R30.2 56.87,54.76 D22.A | R19.1 53.34,59.69 | R4.1 R33.2
  pour Top (isolate 0.813, rank 4, hatched): 50.8,71.12 54.61,71.12 55.88,58.42 57.15,57.47 57.15,51.12 55.88,49.53 52.07,50.8 52.07,59.69
V+
  Top 1.016: 95.25,58.42 97.79,60.96 97.79,78.74 44.45,78.74 | 40.64,78.74 44.45,78.74 | 44.45,78.74 R45.1 | 40.64,78.74 R47.1 | 8.57,69.85 8.57,36.2 11.43,33.02 G1.- D24.C 11.43,17.78 | 8.57,69.85 8.57,72.07 10.79,74.3 | 34.29,77.47 34.29,77.72 | 34.29,77.47 D17.C | 34.29,77.47 35.56,78.74 40.64,78.74 | 22.23,74.3 25.4,77.47 34.29,77.47 | 8.57,69.85 8.32,70.1 F1.2A JP2.1 | D1.C 11.43,17.78 | R41.2 13.97,16.51 12.7,17.78 11.43,17.78
  pour Top (isolate 1.27, rank 2, hatched): 1.27,80.01 99.06,80.01 101.6,77.47 101.6,60.96 88.9,49.53 88.9,29.21 86.36,27.94 64.77,27.94 64.77,23.5 59.05,23.5 59.05,31.75 59.69,33.02 85.09,33.02 85.09,40.64 85.72,43.18 85.72,50.8 87.63,52.07 93.98,58.42 93.98,74.93 92.71,76.2 38.1,76.2 arc-90 35.56,73.66 10.16,73.66 8.89,68.58 8.89,67.31 1.27,67.31
  pour Top (isolate 0.61, rank 3): 10.16,29.21 13.97,29.21 13.97,15.24 11.43,16.51 10.16,17.78
V-
  Top 1.016: D11.A 66.62,50.8 66.62,51.64 | JP1.1 JP3.1 5.08,31.75 5.08,5.08 | Q5.2 73.25,60.68 R27.1 | D19.C Q6.3 | Q7.3 76.2,72.39 76.83,73.03 80.96,74.3 83.67,74.13 R6.2 86.56,71.4 D5.A
  pour Top (isolate 1.27, rank 2, hatched): 0,34.29 10.16,34.29 10.16,3.81 31.75,3.81 31.75,10.16 31.11,11.43 30.48,54.61 31.75,58.42 36.83,58.42 36.83,45.72 38.1,41.91 62.23,43.18 62.23,71.75 76.52,71.75 76.2,57.15 73.66,60.96 72.39,63.5 68.58,63.5 68.58,53.34 70.17,51.44 70.17,47.62 66.04,36.83 41.91,36.83 35.56,30.48 34.29,26.67 34.29,24.13 38.1,22.86 38.1,7.62 45.72,7.62 45.72,22.86 52.07,24.13 52.07,7.62 66.04,7.62 69.85,8.89 90.17,8.89 90.17,1.27 8.89,0 0,1.27
  pour Bottom (isolate 1.27): 1.27,80.01 90.17,80.01 90.17,1.27 1.27,1.27 1.27,2.54
VHIGH
  Top 0.406: 27.94,27.94 28.25,28.25
  Top 1.016: R8.1 17.93,39.37 Q9.E 23.81,39.37 23.81,41.76 Q13.E | R33.1 20.48,52.07 15.24,46.99 15.24,39.37 15.39,39.22 R8.1 | R8.1 17.78,38.1 18.41,36.2 18.41,29.84 19.05,29.21 20.48,28.57 R10.1 23.01,27.94 Q10.E 27.94,27.94 | 28.25,28.25 Q14.E
  pour Top (isolate 0.813, rank 3): 17.78,39.37 15.24,39.37 15.24,46.99 22.86,54.61 24.13,53.34 24.13,52.07 22.86,50.8 21.59,50.8 15.56,46.67 15.56,39.69
  pour Top (isolate 0.813, rank 4, hatched): 24.13,29.21 27.3,26.67 27.3,13.97 26.67,8.89 24.13,10.16

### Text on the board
Top: MICHAEL5.net
Bottom: MICHAELS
